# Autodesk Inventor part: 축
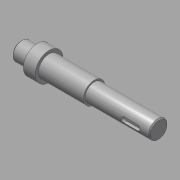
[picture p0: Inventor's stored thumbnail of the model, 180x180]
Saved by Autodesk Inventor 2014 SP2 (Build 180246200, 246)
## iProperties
Created: 2015-09
Part Number: 축
Material: 강철, 연강
Document SubType Name: Modeling
Designer: mduedu
Density: 1 g/cm^3
Appearance: 강철
Author: mduedu
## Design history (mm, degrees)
sketch "스케치1"
  geometry: L1 (-64, 0)-(64, 0); L2 (-64, 0)-(-64, 8.5); L3 (-64, 8.5)-(-49, 8.5); L4 (-49, 8.5)-(-49, 13); L5 (-49, 13)-(-38, 13); L6 (-38, 13)-(-38, 10); L7 (-38, 10)-(4, 10); L8 (4, 10)-(4, 8.5); L9 (4, 8.5)-(64, 8.5); L10 (64, 8.5)-(64, 0); 2 further points
  constraints: 20 end point, 5 parallel, 2 horizontal, 2 perpendicular, 1 coincident, 1 midpoint, 1 vertical
  dimensions: "d0" = 128 distance of L1.start L1.end; "d2" = 11 distance of L4.end L5.end; "d3" = 42 distance of L6.end L7.end; "d4" = 60 distance of L8.end L9.end; "d5" = 17 diameter of L3 L1; "d6" = 17 diameter of L9 L1; "d7" = 20 diameter of L7 L1; "d8" = 26 diameter of L5 L1
revolve "회전1" sketch "스케치1" stored, may be unused: angle "d9" = 90 deg
node "작업 평면1"
sketch "스케치2"
  geometry: L1 (5.5, 2.5)-(18.5, 2.5); L2 (18.5, -2.5)-(5.5, -2.5); L3 (5.5, 2.5)-(18.5, -2.5); L4 (18.5, 2.5)-(5.5, -2.5); L5 (30, -8.5)-(30, 8.5) reference; A1 r 2.5 centre (5.5, 0) between (5.5, 2.5) and (5.5, -2.5); A2 r 2.5 centre (18.5, 0) between (18.5, -2.5) and (18.5, 2.5); 2 further points
  constraints: 8 end point, 4 point on circle, 4 tangent, 2 centre point, 2 midpoint, 1 horizontal, 1 horizontal alignment, 1 parallel
  dimensions: "d10" = 18 dimension on A2 A1; "d12" = 9 distance edge to line of A2 L5; "d13" = 5 distance between parallel lines of L2 L1
extrude "돌출1" cut sketch "스케치2" distance "d14" = 3; taper "d15" = 0 deg
node "작업 평면2"
sketch "스케치4"
  geometry: L1 (7, -3)-(-9, -3); L2 (-9, 3)-(7, 3); L3 (-21, 10)-(-21, -10) reference; A1 r 3 centre (-9, 0) between (-9, 3) and (-9, -3); A2 r 3 centre (7, 0) between (7, -3) and (7, 3); 1 further point
  constraints: 4 end point, 4 point on circle, 4 tangent, 2 centre point, 1 horizontal, 1 horizontal alignment, 1 parallel
  dimensions: "d16" = 22 dimension on A1 A2; "d18" = 6 distance between parallel lines of L2 L1; "d19" = 9 distance edge to line of A1 L3
extrude "돌출2" cut sketch "스케치4" distance "d20" = 3.5; taper "d21" = 0 deg
sketch "스케치5"
  geometry: L1 (4, 8.5)-(64, 8.5) reference; L2 (4, -8.5)-(64, -8.5) reference; L3 (37, 8.5)-(37, -8.5); L4 (37, -6.5)-(35, -8.5); L5 (37, -8.5)-(35, -8.5); L6 (37, -8.5)-(37, -6.5); L7 (4, -10)-(4, 10) reference; 1 further point
  constraints: 8 end point, 4 point on line, 1 collinear, 1 perpendicular
  dimensions: "d22" = 4 diameter of L4.end L3; "d24" = 45 deg angle of L3 L4; "d26" = 33 distance between parallel lines of L3 L7
revolve "회전2" sketch "스케치5" stored, may be unused: angle "d27" = 90 deg
chamfer "모따기1" distance "d28" = 1; stored, may be unused: second distance "d29" = 2, angle "d30" = 45 deg
node "솔리드1"
